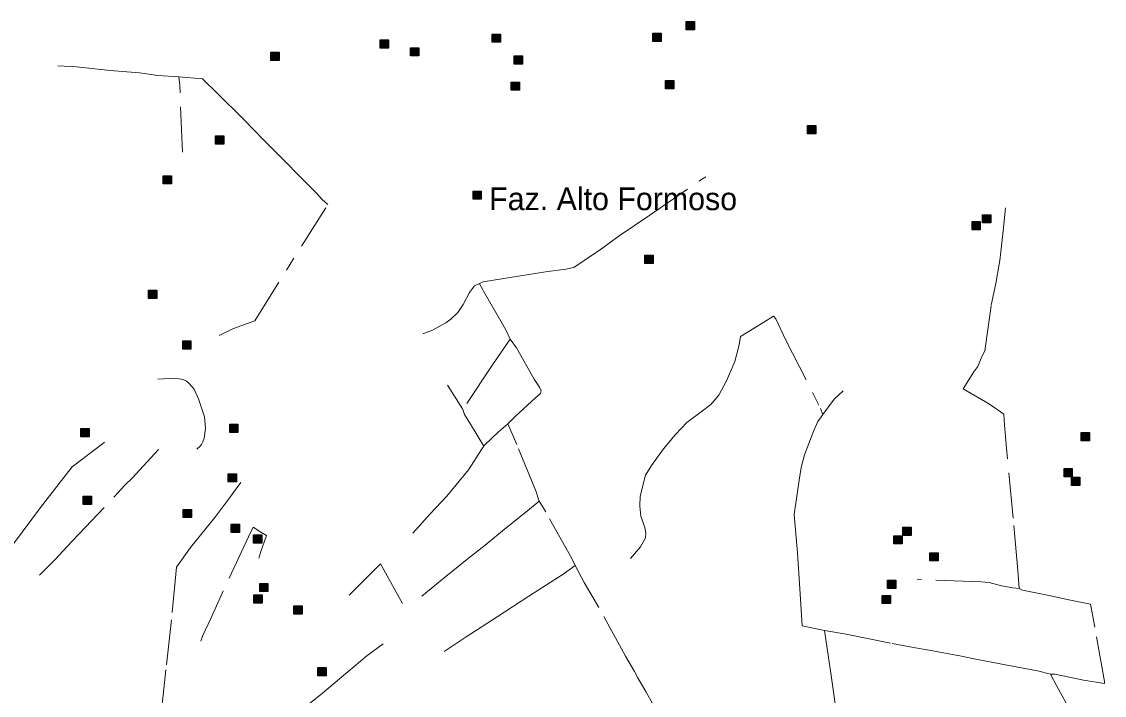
# Model space of a CAD drawing. Extents: x 393.5 to 446.9, y 8064.8 to 8120.4.
# Drawn here: x 410.18 to 417.82, y 8115.35 to 8120.11 of the extents above; entities that cross this region are included whole.
import ezdxf

# ---------------------------------------------------------------- set-up
doc = ezdxf.new("R2010")
doc.units = 0
doc.header["$LTSCALE"] = 0.064
doc.linetypes.add('DOT_DASHED', pattern=[7.7, 5, -1.2, 0.3, -1.2])
doc.layers.add('2', color=7, linetype='Continuous', lineweight=25)
doc.layers.add('22', color=7, linetype='DOT_DASHED', lineweight=13)
doc.layers.add('61', color=7, linetype='Continuous')

msp = doc.modelspace()

# ---------------------------------------------------------------- hatches: boundary and pattern name
at = {"layer": '2'}
for points in [[(414.8678, 8120.1078), (414.9258, 8120.1078), (414.9258, 8120.0498), (414.8678, 8120.0498)], [(413.5013, 8120.0203), (413.5593, 8120.0203), (413.5593, 8119.9623), (413.5013, 8119.9623)], [(414.6333, 8120.0259), (414.6913, 8120.0259), (414.6913, 8119.9679), (414.6333, 8119.9679)], [(412.7115, 8119.9789), (412.7695, 8119.9789), (412.7695, 8119.9209), (412.7115, 8119.9209)], [(411.9409, 8119.8916), (411.9989, 8119.8916), (411.9989, 8119.8336), (411.9409, 8119.8336)], [(412.9257, 8119.9237), (412.9837, 8119.9237), (412.9837, 8119.8657), (412.9257, 8119.8657)], [(413.6555, 8119.866), (413.7135, 8119.866), (413.7135, 8119.808), (413.6555, 8119.808)], [(413.6349, 8119.6813), (413.6929, 8119.6813), (413.6929, 8119.6233), (413.6349, 8119.6233)], [(414.7234, 8119.6927), (414.7814, 8119.6927), (414.7814, 8119.6347), (414.7234, 8119.6347)], [(415.7243, 8119.3748), (415.7823, 8119.3748), (415.7823, 8119.3168), (415.7243, 8119.3168)], [(411.5502, 8119.3014), (411.6082, 8119.3014), (411.6082, 8119.2434), (411.5502, 8119.2434)], [(411.181, 8119.0208), (411.239, 8119.0208), (411.239, 8118.9628), (411.181, 8118.9628)], [(413.3655, 8118.9128), (413.4235, 8118.9128), (413.4235, 8118.8548), (413.3655, 8118.8548)], [(416.9566, 8118.7455), (417.0146, 8118.7455), (417.0146, 8118.6875), (416.9566, 8118.6875)], [(416.8828, 8118.6975), (416.9408, 8118.6975), (416.9408, 8118.6395), (416.8828, 8118.6395)], [(414.5775, 8118.46), (414.6355, 8118.46), (414.6355, 8118.402), (414.5775, 8118.402)], [(411.0782, 8118.2132), (411.1362, 8118.2132), (411.1362, 8118.1552), (411.0782, 8118.1552)], [(411.319, 8117.855), (411.377, 8117.855), (411.377, 8117.797), (411.319, 8117.797)], [(411.6506, 8117.2677), (411.7086, 8117.2677), (411.7086, 8117.2097), (411.6506, 8117.2097)], [(410.6009, 8117.2364), (410.6589, 8117.2364), (410.6589, 8117.1784), (410.6009, 8117.1784)], [(417.6522, 8117.2091), (417.7102, 8117.2091), (417.7102, 8117.1511), (417.6522, 8117.1511)], [(417.5314, 8116.9538), (417.5894, 8116.9538), (417.5894, 8116.8958), (417.5314, 8116.8958)], [(411.6403, 8116.9178), (411.6983, 8116.9178), (411.6983, 8116.8598), (411.6403, 8116.8598)], [(417.5849, 8116.894), (417.6429, 8116.894), (417.6429, 8116.836), (417.5849, 8116.836)], [(410.6176, 8116.7588), (410.6756, 8116.7588), (410.6756, 8116.7008), (410.6176, 8116.7008)], [(411.3218, 8116.6667), (411.3798, 8116.6667), (411.3798, 8116.6087), (411.3218, 8116.6087)], [(411.6604, 8116.561), (411.7184, 8116.561), (411.7184, 8116.503), (411.6604, 8116.503)], [(416.3948, 8116.5404), (416.4528, 8116.5404), (416.4528, 8116.4824), (416.3948, 8116.4824)], [(411.8179, 8116.487), (411.8759, 8116.487), (411.8759, 8116.429), (411.8179, 8116.429)], [(416.3314, 8116.4803), (416.3894, 8116.4803), (416.3894, 8116.4223), (416.3314, 8116.4223)], [(416.5858, 8116.3608), (416.6438, 8116.3608), (416.6438, 8116.3028), (416.5858, 8116.3028)], [(411.8619, 8116.144), (411.9199, 8116.144), (411.9199, 8116.086), (411.8619, 8116.086)], [(416.2879, 8116.1666), (416.3459, 8116.1666), (416.3459, 8116.1086), (416.2879, 8116.1086)], [(411.8214, 8116.0631), (411.8794, 8116.0631), (411.8794, 8116.0051), (411.8214, 8116.0051)], [(416.2506, 8116.0597), (416.3086, 8116.0597), (416.3086, 8116.0017), (416.2506, 8116.0017)], [(412.1029, 8115.9852), (412.1609, 8115.9852), (412.1609, 8115.9272), (412.1029, 8115.9272)], [(412.2712, 8115.5509), (412.3292, 8115.5509), (412.3292, 8115.4929), (412.2712, 8115.4929)]]:
    msp.add_hatch(color=256, dxfattribs=at).paths.add_polyline_path(points)

# ---------------------------------------------------------------- linework, layer by layer
for points in [[(414.8678, 8120.1078), (414.9258, 8120.1078), (414.9258, 8120.0498), (414.8678, 8120.0498)], [(413.5013, 8120.0203), (413.5593, 8120.0203), (413.5593, 8119.9623), (413.5013, 8119.9623)], [(414.6333, 8120.0259), (414.6913, 8120.0259), (414.6913, 8119.9679), (414.6333, 8119.9679)], [(412.7115, 8119.9789), (412.7695, 8119.9789), (412.7695, 8119.9209), (412.7115, 8119.9209)], [(411.9409, 8119.8916), (411.9989, 8119.8916), (411.9989, 8119.8336), (411.9409, 8119.8336)], [(412.9257, 8119.9237), (412.9837, 8119.9237), (412.9837, 8119.8657), (412.9257, 8119.8657)], [(413.6555, 8119.866), (413.7135, 8119.866), (413.7135, 8119.808), (413.6555, 8119.808)], [(413.6349, 8119.6813), (413.6929, 8119.6813), (413.6929, 8119.6233), (413.6349, 8119.6233)], [(414.7234, 8119.6927), (414.7814, 8119.6927), (414.7814, 8119.6347), (414.7234, 8119.6347)], [(415.7243, 8119.3748), (415.7823, 8119.3748), (415.7823, 8119.3168), (415.7243, 8119.3168)], [(411.5502, 8119.3014), (411.6082, 8119.3014), (411.6082, 8119.2434), (411.5502, 8119.2434)], [(411.181, 8119.0208), (411.239, 8119.0208), (411.239, 8118.9628), (411.181, 8118.9628)], [(413.3655, 8118.9128), (413.4235, 8118.9128), (413.4235, 8118.8548), (413.3655, 8118.8548)], [(416.9566, 8118.7455), (417.0146, 8118.7455), (417.0146, 8118.6875), (416.9566, 8118.6875)], [(416.8828, 8118.6975), (416.9408, 8118.6975), (416.9408, 8118.6395), (416.8828, 8118.6395)], [(414.5775, 8118.46), (414.6355, 8118.46), (414.6355, 8118.402), (414.5775, 8118.402)], [(411.0782, 8118.2132), (411.1362, 8118.2132), (411.1362, 8118.1552), (411.0782, 8118.1552)], [(411.319, 8117.855), (411.377, 8117.855), (411.377, 8117.797), (411.319, 8117.797)], [(411.6506, 8117.2677), (411.7086, 8117.2677), (411.7086, 8117.2097), (411.6506, 8117.2097)], [(410.6009, 8117.2364), (410.6589, 8117.2364), (410.6589, 8117.1784), (410.6009, 8117.1784)], [(417.6522, 8117.2091), (417.7102, 8117.2091), (417.7102, 8117.1511), (417.6522, 8117.1511)], [(417.5314, 8116.9538), (417.5894, 8116.9538), (417.5894, 8116.8958), (417.5314, 8116.8958)], [(411.6403, 8116.9178), (411.6983, 8116.9178), (411.6983, 8116.8598), (411.6403, 8116.8598)], [(417.5849, 8116.894), (417.6429, 8116.894), (417.6429, 8116.836), (417.5849, 8116.836)], [(410.6176, 8116.7588), (410.6756, 8116.7588), (410.6756, 8116.7008), (410.6176, 8116.7008)], [(411.3218, 8116.6667), (411.3798, 8116.6667), (411.3798, 8116.6087), (411.3218, 8116.6087)], [(411.6604, 8116.561), (411.7184, 8116.561), (411.7184, 8116.503), (411.6604, 8116.503)], [(416.3948, 8116.5404), (416.4528, 8116.5404), (416.4528, 8116.4824), (416.3948, 8116.4824)], [(411.8179, 8116.487), (411.8759, 8116.487), (411.8759, 8116.429), (411.8179, 8116.429)], [(416.3314, 8116.4803), (416.3894, 8116.4803), (416.3894, 8116.4223), (416.3314, 8116.4223)], [(416.5858, 8116.3608), (416.6438, 8116.3608), (416.6438, 8116.3028), (416.5858, 8116.3028)], [(411.8619, 8116.144), (411.9199, 8116.144), (411.9199, 8116.086), (411.8619, 8116.086)], [(416.2879, 8116.1666), (416.3459, 8116.1666), (416.3459, 8116.1086), (416.2879, 8116.1086)], [(411.8214, 8116.0631), (411.8794, 8116.0631), (411.8794, 8116.0051), (411.8214, 8116.0051)], [(416.2506, 8116.0597), (416.3086, 8116.0597), (416.3086, 8116.0017), (416.2506, 8116.0017)], [(412.1029, 8115.9852), (412.1609, 8115.9852), (412.1609, 8115.9272), (412.1029, 8115.9272)], [(412.2712, 8115.5509), (412.3292, 8115.5509), (412.3292, 8115.4929), (412.2712, 8115.4929)]]:
    msp.add_lwpolyline(points, close=True, dxfattribs=at)
at = {"layer": '22'}
msp.add_line((411.5762, 8117.8926), (411.676, 8117.9418), dxfattribs=at)
for points in [[(410.4398, 8119.7964), (410.5695, 8119.7899), (410.8068, 8119.7633), (411.0154, 8119.7469), (411.1443, 8119.7285), (411.2925, 8119.7183)], [(411.3178, 8119.1861), (411.2977, 8119.659), (411.2925, 8119.7183)], [(412.3043, 8118.8515), (412.259, 8118.8992), (412.1655, 8118.9941), (412.01, 8119.1515), (411.8913, 8119.2721), (411.8177, 8119.3457), (411.7426, 8119.424), (411.5667, 8119.5977), (411.4582, 8119.704), (411.2925, 8119.7183)], [(414.2536, 8118.4932), (414.3948, 8118.5958), (414.6128, 8118.743), (414.979, 8118.9958), (415.0059, 8119.0128)], [(411.676, 8117.9418), (411.8269, 8117.9976), (412.3417, 8118.8173), (412.3192, 8118.8377), (412.3043, 8118.8515)], [(417.075, 8118.3976), (417.0799, 8118.4219), (417.0854, 8118.4846), (417.1022, 8118.631), (417.1194, 8118.795)], [(413.4103, 8118.261), (413.4381, 8118.2708), (413.6999, 8118.3132), (413.8768, 8118.3415), (414.0197, 8118.3613), (414.0749, 8118.3726), (414.2221, 8118.473), (414.2536, 8118.4932)], [(416.9523, 8117.7442), (416.9733, 8117.7862), (417.0183, 8118.1083), (417.0507, 8118.2608), (417.075, 8118.3976)], [(413.3699, 8118.2342), (413.3763, 8118.2426), (413.4103, 8118.261)], [(413.6269, 8117.868), (413.5977, 8117.933), (413.4343, 8118.2158), (413.412, 8118.2577), (413.4108, 8118.26), (413.4103, 8118.261)], [(413.0105, 8117.9047), (413.0798, 8117.9301), (413.1732, 8117.9825), (413.21, 8118.0093), (413.2595, 8118.056), (413.2963, 8118.1126), (413.3416, 8118.196), (413.3699, 8118.2342)], [(414.4745, 8116.3197), (414.5461, 8116.4016), (414.581, 8116.466), (414.5847, 8116.4991), (414.5773, 8116.5395), (414.5479, 8116.6186), (414.5405, 8116.6884), (414.5442, 8116.7601), (414.5801, 8116.9072), (414.6224, 8116.9771), (414.7089, 8117.0947), (414.7935, 8117.194), (414.8736, 8117.2804), (414.9729, 8117.3539), (415.0428, 8117.4054), (415.098, 8117.4716), (415.1523, 8117.5727), (415.2112, 8117.7106), (415.2406, 8117.8264), (415.2507, 8117.8852), (415.3464, 8117.9458), (415.4825, 8118.0304), (415.4991, 8118.0102), (415.569, 8117.8649), (415.8157, 8117.3778), (415.8317, 8117.3367)], [(413.6269, 8117.868), (413.4988, 8117.6792), (413.294, 8117.3724), (413.2934, 8117.3714)], [(413.6104, 8117.2701), (413.6628, 8117.3211), (413.8069, 8117.4536), (413.8417, 8117.4848), (413.8467, 8117.504), (413.8339, 8117.5294), (413.7972, 8117.5846), (413.6712, 8117.8066), (413.6269, 8117.868)], [(417.2152, 8116.1079), (417.2055, 8116.2347), (417.1731, 8116.6047), (417.125, 8117.0982), (417.1154, 8117.207), (417.113, 8117.2619), (417.108, 8117.3392), (417.0068, 8117.4079), (416.8216, 8117.5166), (416.8961, 8117.6368), (416.9228, 8117.6749), (416.9523, 8117.7442)], [(411.4004, 8117.5145), (411.3675, 8117.553), (411.3447, 8117.5721), (411.3219, 8117.5836), (411.2932, 8117.5874), (411.2285, 8117.5895), (411.1827, 8117.5877), (411.1429, 8117.5856)], [(411.4194, 8117.0909), (411.4419, 8117.1118), (411.4514, 8117.1251), (411.4609, 8117.1441), (411.4704, 8117.1688), (411.4787, 8117.2372), (411.4724, 8117.3185), (411.4307, 8117.4457), (411.4057, 8117.4979), (411.4004, 8117.5145)], [(413.186, 8117.5429), (413.2912, 8117.3749), (413.2934, 8117.3714)], [(415.8317, 8117.3367), (415.9114, 8117.444), (415.9739, 8117.5029)], [(413.4405, 8117.1131), (413.3487, 8117.2671), (413.3062, 8117.335), (413.2934, 8117.3714)], [(415.7022, 8117.0518), (415.7323, 8117.1302), (415.7669, 8117.2234), (415.7965, 8117.287), (415.8317, 8117.3367)], [(413.4405, 8117.113), (413.4437, 8117.1183), (413.5456, 8117.2146), (413.6104, 8117.2701)], [(413.8314, 8116.7252), (413.8082, 8116.7983), (413.6737, 8117.1236), (413.6104, 8117.2701)], [(410.7672, 8117.1408), (410.7528, 8117.1278), (410.5387, 8116.9665), (410.4972, 8116.912), (410.3175, 8116.6797), (410.071, 8116.3467), (409.9837, 8116.2312), (409.9078, 8116.1376), (409.8671, 8116.0796), (409.8512, 8116.0652), (409.8511, 8116.0651)], [(412.9403, 8116.4994), (413.064, 8116.636), (413.1816, 8116.7606), (413.3338, 8116.9457), (413.4254, 8117.088), (413.4405, 8117.113)], [(410.9121, 8116.8366), (410.962, 8116.8878), (411.1475, 8117.0879)], [(415.8432, 8115.8113), (415.6847, 8115.8442), (415.6682, 8116.1052), (415.6525, 8116.3608), (415.6295, 8116.631), (415.6635, 8116.8737), (415.6782, 8116.9619), (415.7022, 8117.0518)], [(410.5456, 8116.4479), (410.8645, 8116.786), (410.9121, 8116.8366)], [(411.2761, 8116.2577), (411.375, 8116.3973), (411.5463, 8116.6088), (411.638, 8116.7314), (411.7297, 8116.8568)], [(413.8314, 8116.7252), (413.7379, 8116.6478), (413.5989, 8116.5362), (413.4506, 8116.4151), (413.3329, 8116.322), (413.161, 8116.1846), (413.0049, 8116.0532)], [(414.086, 8116.2715), (414.0612, 8116.3192), (413.8776, 8116.6487), (413.8314, 8116.7252)], [(411.8556, 8116.3226), (411.8701, 8116.3691), (411.9086, 8116.482), (411.8701, 8116.5063), (411.8146, 8116.5402), (411.783, 8116.4717), (411.5969, 8116.0746), (411.5178, 8115.8954), (411.4581, 8115.7721), (411.4465, 8115.7374)], [(410.3088, 8116.2013), (410.4183, 8116.3103), (410.5373, 8116.4395), (410.5456, 8116.4479)], [(412.4924, 8116.06), (412.714, 8116.282), (412.8738, 8115.9941)], [(414.086, 8116.2715), (414.0018, 8116.209), (413.7593, 8116.0533), (413.5357, 8115.9093), (413.309, 8115.7618), (413.1623, 8115.6643)], [(414.5028, 8115.5224), (414.4409, 8115.6308), (414.2522, 8115.9747), (414.1488, 8116.1509), (414.086, 8116.2715)], [(411.2761, 8116.2577), (411.2398, 8115.888), (411.1999, 8115.535), (411.181, 8115.3547), (411.1208, 8114.7887), (411.1018, 8114.6125)], [(417.2152, 8116.1079), (417.1707, 8116.1119), (417.0906, 8116.1271), (417.0028, 8116.15), (416.9466, 8116.155), (416.4969, 8116.1729)], [(417.4365, 8115.504), (417.4673, 8115.5034), (417.6696, 8115.4609), (417.8157, 8115.4388), (417.8157, 8115.4524), (417.7495, 8115.8363), (417.7189, 8115.9977), (417.5779, 8116.0266), (417.3926, 8116.0657), (417.2394, 8116.0966), (417.2152, 8116.1079)], [(415.8432, 8115.8113), (415.9947, 8115.7855), (416.3202, 8115.72), (416.4711, 8115.6924), (416.5815, 8115.6722), (416.8096, 8115.6299), (416.8869, 8115.6134), (417.0322, 8115.5858), (417.2052, 8115.5527), (417.345, 8115.527), (417.4351, 8115.5043), (417.4365, 8115.504)], [(417.4196, 8115.1753), (417.1289, 8115.2452), (417.0932, 8115.2163), (416.8425, 8114.9734), (416.5646, 8114.705), (416.5578, 8114.7067), (416.534, 8114.7135), (416.0674, 8114.9224), (415.9672, 8114.9717), (415.9307, 8115.213), (415.8879, 8115.5118), (415.8432, 8115.8113)], [(412.7316, 8115.7173), (412.6162, 8115.6321), (412.4375, 8115.4816), (412.2905, 8115.358), (412.1208, 8115.223), (411.9325, 8115.0664), (411.8511, 8115.001), (411.7923, 8114.9492), (411.8715, 8114.8157), (411.9327, 8114.7117), (412.009, 8114.5255), (412.0108, 8114.5212)], [(414.6705, 8115.2225), (414.6316, 8115.2957), (414.5865, 8115.3768), (414.5269, 8115.4781), (414.5028, 8115.5224)], [(417.5809, 8115.2364), (417.4797, 8115.4193), (417.4368, 8115.5034), (417.4365, 8115.504)]]:
    msp.add_lwpolyline(points, dxfattribs=at)

# ---------------------------------------------------------------- texts
at = {"layer": '61'}
msp.add_text('Faz. Alto Formoso', height=0.16, dxfattribs=at).set_placement((413.4791, 8118.7776))

doc.saveas('drawing.dxf')
